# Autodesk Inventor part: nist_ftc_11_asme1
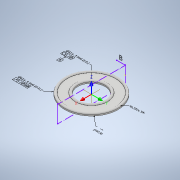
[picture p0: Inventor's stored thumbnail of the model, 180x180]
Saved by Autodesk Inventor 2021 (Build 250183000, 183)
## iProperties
Created: 2016-11
Part Number: nist_ftc_11_asme1
Material: Generic
Document SubType Name: Modeling
Designer: t_liuje
Density: 1 g/cm^3
Appearance: Default
Author: t_liuje
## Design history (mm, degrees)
sketch "Sketch1"
  geometry: L1 (0, -5.07)-(0, 4.863); L2 (16, 0)-(31.5, 0); L3 (31.5, 0)-(31.5, 1.5); L4 (16, 0)-(16, 1.5); L5 (28.561, 1.925)-(18.979, 1.925); A1 r 1.5 centre (30, 1.5) between (31.5, 1.5) and (28.561, 1.925); A2 r 1.52 centre (17.52, 1.5) between (18.979, 1.925) and (16, 1.5); 1 further point
  constraints: 10 end point, 4 point on circle, 2 centre point, 2 horizontal, 2 point on line, 2 tangent, 2 vertical, 1 perpendicular
  dimensions: "d0" = 15.5 distance of L2.start L2.end; "d1" = 32 diameter of L2.start L1; "d2" = 1.5 distance of L2.end L3.end; "d3" = 3 diameter of A1; "d4" = 3.04 diameter of A2; "d5" = 1.925 distance between parallel lines of L2 L5; "d6" = 1.5 distance from line of L2 A2.centre
revolve "Revolution1" sketch "Sketch1" stored, may be unused: angle "d7" = 90 deg
fillet "Fillet1" dims "d43" = 0.1
sketch "3D Sketch1"
workplane "Work Plane1"
sketch "Sketch3"
  geometry: L1 (7.272, -7.308)-(1.868, -7.308); L2 (1.868, -7.308)-(1.868, -4.066); L3 (1.868, -4.066)-(7.272, -4.066); L4 (7.272, -4.066)-(7.272, -7.308); 1 further point
  constraints: 2 other
body "Solid1"
node "Annotations"
node "Tolerance Features"
node "Radial Dimension 1" dims "d0" = 15.5, "d1" = 32, "d2" = 1.5, "d3" = 3, "d4" = 3.04, "d5" = 1.925, "d6" = 1.5, "d12" = 1.5 (derived)
node "Planar Surface 1" dims "d10" = 7.50929 (derived), "d11" = 9.84087 (derived), "d12" = 1.5 (derived), "d19" = 6.32869 (derived), "d20" = 8.89083 (derived), "d21" = 1.925 (derived), "d44" = 4.96728 (derived), "d45" = 2.51115 (derived), "d46" = 0.1 (derived), "d68" = 3.58239 (derived), "d69" = 2.03739 (derived), "d70" = 0.3 (derived), "d71" = 0 (derived), "d72" = 0 (derived), "d87" = 3.75432 (derived), "d88" = 8.96323 (derived), "d89" = 0.3 (derived), "d90" = 0 (derived), "d91" = 0 (derived), "d127" = 58.81845 (derived), "d128" = 23.55344 (derived), "d129" = 32 (derived), "d130" = 1.2 (derived), "d131" = 0 (derived)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
node "Datum Reference Frame 1"
node "Linear Dimension 1" dims "d0" = 15.5, "d1" = 32, "d2" = 1.5, "d3" = 3, "d4" = 3.04, "d5" = 1.925, "d6" = 1.5, "d21" = 1.925 (derived)
node "Simple Hole 1" dims "d10" = 7.50929 (derived), "d11" = 9.84087 (derived), "d12" = 1.5 (derived), "d19" = 6.32869 (derived), "d20" = 8.89083 (derived), "d21" = 1.925 (derived), "d44" = 4.96728 (derived), "d45" = 2.51115 (derived), "d46" = 0.1 (derived), "d68" = 3.58239 (derived), "d69" = 2.03739 (derived), "d70" = 0.3 (derived), "d71" = 0 (derived), "d72" = 0 (derived), "d87" = 3.75432 (derived), "d88" = 8.96323 (derived), "d89" = 0.3 (derived), "d90" = 0 (derived), "d91" = 0 (derived), "d127" = 58.81845 (derived), "d128" = 23.55344 (derived), "d129" = 32 (derived), "d130" = 1.2 (derived), "d131" = 0 (derived)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
node "Datum Reference Frame 2"
node "Shaft 1"
node "Planar Surface 2"
node "Radial Dimension 2" dims "d0" = 15.5, "d1" = 32, "d2" = 1.5, "d3" = 3, "d4" = 3.04, "d5" = 1.925, "d6" = 1.5, "d46" = 0.1 (derived)
node "General Note 1"
node "Feature Control Frame 1"
node "Datum Identifier 3" dims "d10" = 7.50929 (derived), "d11" = 9.84087 (derived), "d12" = 1.5 (derived), "d19" = 6.32869 (derived), "d20" = 8.89083 (derived), "d21" = 1.925 (derived), "d44" = 4.96728 (derived), "d45" = 2.51115 (derived), "d46" = 0.1 (derived), "d68" = 3.58239 (derived), "d69" = 2.03739 (derived), "d70" = 0.3 (derived), "d71" = 0 (derived), "d72" = 0 (derived), "d87" = 3.75432 (derived), "d88" = 8.96323 (derived), "d89" = 0.3 (derived), "d90" = 0 (derived), "d91" = 0 (derived), "d127" = 58.81845 (derived), "d128" = 23.55344 (derived), "d129" = 32 (derived), "d130" = 1.2 (derived), "d131" = 0 (derived)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
node "Feature Control Frame 4"
node "Diameter Dimension 2" dims "d0" = 15.5, "d1" = 32, "d2" = 1.5, "d3" = 3, "d4" = 3.04, "d5" = 1.925, "d6" = 1.5, "d129" = 32 (derived)
node "Feature Control Frame 12"
node "Datum Identifier 4" dims "d10" = 7.50929 (derived), "d11" = 9.84087 (derived), "d12" = 1.5 (derived), "d19" = 6.32869 (derived), "d20" = 8.89083 (derived), "d21" = 1.925 (derived), "d44" = 4.96728 (derived), "d45" = 2.51115 (derived), "d46" = 0.1 (derived), "d68" = 3.58239 (derived), "d69" = 2.03739 (derived), "d70" = 0.3 (derived), "d71" = 0 (derived), "d72" = 0 (derived), "d87" = 3.75432 (derived), "d88" = 8.96323 (derived), "d89" = 0.3 (derived), "d90" = 0 (derived), "d91" = 0 (derived), "d127" = 58.81845 (derived), "d128" = 23.55344 (derived), "d129" = 32 (derived), "d130" = 1.2 (derived), "d131" = 0 (derived)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
node "Diameter Dimension 3" dims "d0" = 15.5, "d1" = 32, "d2" = 1.5, "d3" = 3, "d4" = 3.04, "d5" = 1.925, "d6" = 1.5, "d147" = 63 (derived)
node "Feature Control Frame 13"
node "Diameter Dimension 13" dims "d0" = 15.5, "d1" = 32, "d2" = 1.5, "d3" = 3, "d4" = 3.04, "d5" = 1.925, "d6" = 1.5, "d156" = 63 (derived)
other parameters: "d56" = 0, "d57" = 0, "d58" = 0, "d59" = 0, "d60" = 0, "d61" = 90 deg
